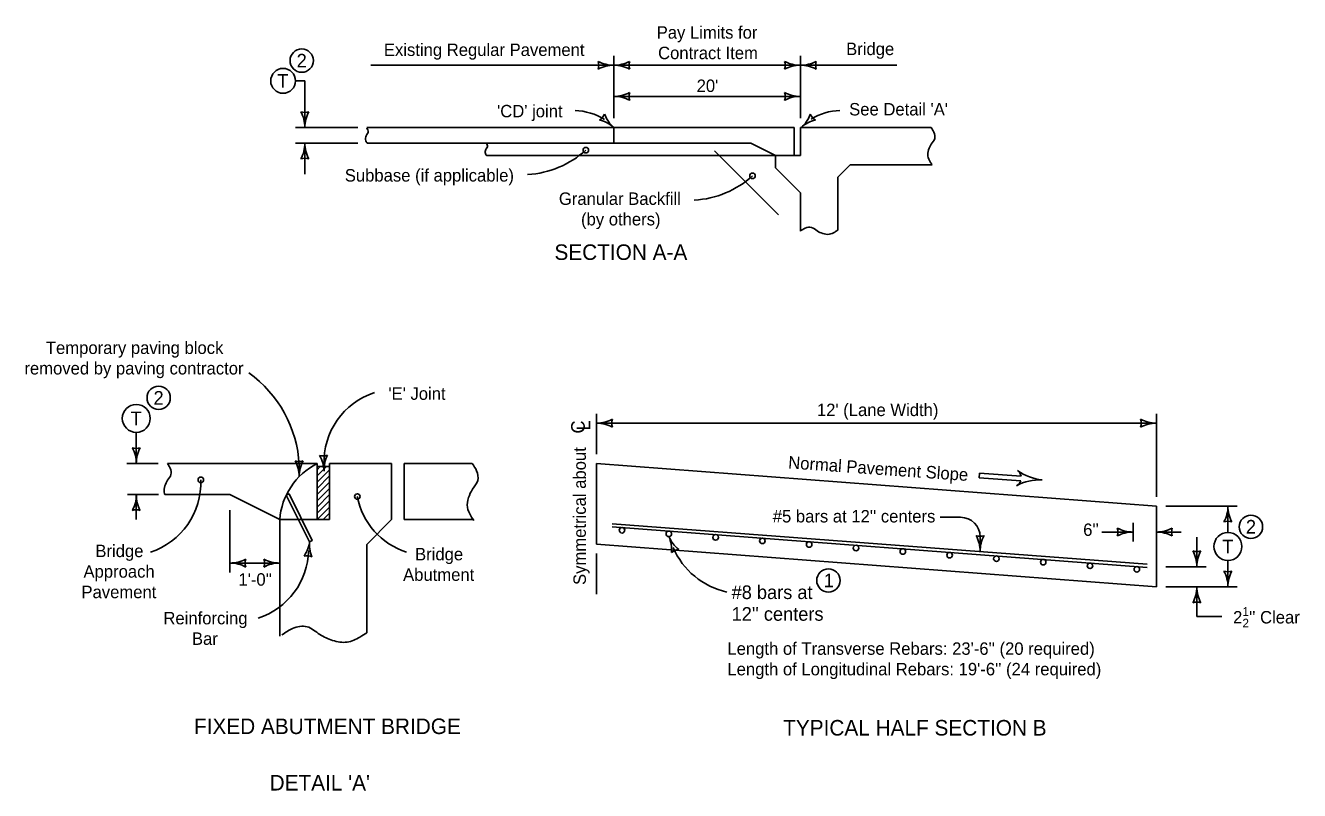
# Model space of a CAD drawing. Extents: x -2134222 to -2124595, y -2139046 to -2134021.
# Drawn here: x -2134222 to -2132583, y -2138902 to -2137918 of the extents above; entities that cross this region are included whole.
import ezdxf

# ---------------------------------------------------------------- set-up
doc = ezdxf.new("R2010")
doc.units = 0
for name, color, linetype in [('Barrier', 7, 'Continuous'), ('BridgeSuperStructureExisting', 7, 'Continuous'), ('dsnStdLabel', 7, 'Continuous'), ('hwyPlanSheetShape', 7, 'Continuous')]:
    doc.layers.add(name, color=color, linetype=linetype)

msp = doc.modelspace()

# ---------------------------------------------------------------- linework, layer by layer
at = {"layer": 'BridgeSuperStructureExisting'}
for p, q in [((-2133465.2, -2137957.4), (-2133465.2, -2138037.4)), ((-2133225.2, -2137957.4), (-2133225.2, -2138037.4)), ((-2133777.7, -2137969.4), (-2133465.2, -2137969.4)), ((-2133465.2, -2137969.4), (-2133225.2, -2137969.4)), ((-2133225.2, -2137969.4), (-2133101.2, -2137969.4)), ((-2133862.6, -2137989.4), (-2133874.6, -2137989.4)), ((-2133862.6, -2137989.4), (-2133862.6, -2138049.4)), ((-2133465.2, -2138009.4), (-2133225.2, -2138009.4)), ((-2133794.6, -2138049.4), (-2133874.6, -2138049.4)), ((-2133783.1, -2138049.4), (-2133465.2, -2138049.4)), ((-2133465.2, -2138049.4), (-2133233.2, -2138049.4)), ((-2133465.2, -2138049.4), (-2133465.2, -2138069.4)), ((-2133233.2, -2138049.4), (-2133233.2, -2138085.4)), ((-2133225.2, -2138085.4), (-2133225.2, -2138049.4)), ((-2133225.2, -2138049.4), (-2133057.2, -2138049.4)), ((-2133794.6, -2138069.4), (-2133874.6, -2138069.4)), ((-2133862.6, -2138069.4), (-2133862.6, -2138109.4)), ((-2133782.6, -2138069.4), (-2133465.2, -2138069.4)), ((-2133465.2, -2138069.4), (-2133289.2, -2138069.4)), ((-2133335.8, -2138079.3), (-2133253.4, -2138161.6)), ((-2133257.2, -2138085.4), (-2133289.2, -2138069.4)), ((-2133629, -2138085.4), (-2133257.2, -2138085.4)), ((-2133233.2, -2138085.4), (-2133257.2, -2138085.4)), ((-2133257.2, -2138085.4), (-2133257.2, -2138101.4)), ((-2133233.2, -2138085.4), (-2133225.2, -2138085.4)), ((-2133257.2, -2138101.4), (-2133225.2, -2138133.4)), ((-2133177.2, -2138113.4), (-2133161.2, -2138097.4)), ((-2133161.2, -2138097.4), (-2133055.9, -2138097.4)), ((-2133177.2, -2138113.4), (-2133177.2, -2138181.4)), ((-2133225.2, -2138133.4), (-2133225.2, -2138182.6)), ((-2133487.3, -2138469.6), (-2133487.3, -2138417.6)), ((-2132767.3, -2138522.4), (-2132767.3, -2138417.6)), ((-2132767.3, -2138524.2), (-2132767.3, -2138419.5)), ((-2133487.3, -2138429.6), (-2132767.3, -2138429.6)), ((-2134079.5, -2138441.5), (-2134079.5, -2138481.5)), ((-2134051.5, -2138481.5), (-2134091.5, -2138481.5)), ((-2134039.5, -2138481.5), (-2133847, -2138481.5)), ((-2133869.9, -2138483.3), (-2133869.9, -2138498.4)), ((-2133847, -2138481.5), (-2133847, -2138553.5)), ((-2133847, -2138497.5), (-2133835, -2138485.5)), ((-2133847, -2138489.5), (-2133843, -2138485.5)), ((-2133847, -2138485.5), (-2133831, -2138485.5)), ((-2133831, -2138553.5), (-2133831, -2138481.5)), ((-2133831, -2138481.5), (-2133751, -2138481.5)), ((-2133751, -2138553.5), (-2133751, -2138481.5)), ((-2133735, -2138481.5), (-2133647.5, -2138481.5)), ((-2133735, -2138553.5), (-2133735, -2138481.5)), ((-2133487.3, -2138481.6), (-2132767.3, -2138536.2)), ((-2133487.3, -2138481.6), (-2133487.3, -2138585.3)), ((-2133847, -2138505.5), (-2133831, -2138489.5)), ((-2133847, -2138513.5), (-2133831, -2138497.5)), ((-2133847, -2138521.5), (-2133831, -2138505.5)), ((-2132995.4, -2138500), (-2132995, -2138493.9)), ((-2132941.8, -2138503.7), (-2132995.4, -2138500)), ((-2132995, -2138493.9), (-2132941.3, -2138497.6)), ((-2134050.9, -2138521.5), (-2134090.9, -2138521.5)), ((-2134079.5, -2138521.5), (-2134079.5, -2138553.5)), ((-2134042.6, -2138521.5), (-2133959, -2138521.5)), ((-2133895, -2138553.5), (-2133959, -2138521.5)), ((-2133847, -2138529.5), (-2133831, -2138513.5)), ((-2133847, -2138537.5), (-2133831, -2138521.5)), ((-2133847, -2138545.5), (-2133831, -2138529.5)), ((-2133847, -2138553.5), (-2133831, -2138537.5)), ((-2132767.3, -2138536.2), (-2132767.3, -2138639.9)), ((-2132755.3, -2138536.2), (-2132663.3, -2138536.2)), ((-2132675.3, -2138570.2), (-2132675.3, -2138536.2)), ((-2133959, -2138541.5), (-2133959, -2138621.5)), ((-2133847, -2138553.5), (-2133895, -2138553.5)), ((-2133895, -2138553.5), (-2133895, -2138703.5)), ((-2133847, -2138553.5), (-2133831, -2138553.5)), ((-2133839, -2138553.5), (-2133831, -2138545.5)), ((-2133783, -2138585.5), (-2133751, -2138553.5)), ((-2133735, -2138553.5), (-2133645.4, -2138553.5)), ((-2133045.3, -2138550.7), (-2133019.1, -2138550.7)), ((-2133467.5, -2138558.9), (-2132779.4, -2138611.1)), ((-2133467.4, -2138562.9), (-2132779.3, -2138615.1)), ((-2132837.5, -2138569.6), (-2132797.3, -2138569.6)), ((-2132797.3, -2138581.6), (-2132797.3, -2138557.6)), ((-2132767.3, -2138569.6), (-2132735.3, -2138569.6)), ((-2133783, -2138585.5), (-2133783, -2138699.1)), ((-2133487.3, -2138585.3), (-2132767.3, -2138639.9)), ((-2132994.1, -2138594.6), (-2132994.1, -2138575.7)), ((-2132715.3, -2138614.2), (-2132715.3, -2138576.2)), ((-2133895, -2138597.5), (-2133895, -2138621.5)), ((-2133487.3, -2138649.3), (-2133487.3, -2138597.3)), ((-2133895, -2138609.5), (-2133959, -2138609.5)), ((-2132792.2, -2138610.1), (-2132792.2, -2138610.1)), ((-2132755.3, -2138614.2), (-2132703.3, -2138614.2)), ((-2132675.3, -2138640.2), (-2132675.3, -2138606.2)), ((-2132755.3, -2138640.2), (-2132663.3, -2138640.2)), ((-2132715.3, -2138678.2), (-2132715.3, -2138640.2)), ((-2132715.3, -2138678.2), (-2132683.3, -2138678.2))]:
    msp.add_line(p, q, dxfattribs=at)
msp.add_lwpolyline([(-2133886.6, -2138522.3), (-2133883, -2138520.5), (-2133853.1, -2138580.3), (-2133856.7, -2138582.1)], close=True, dxfattribs=at)
for centre, radius in [((-2133866.7, -2137963.4), 15), ((-2133890.6, -2137989.4), 16), ((-2133501.2, -2138078.5), 3.56), ((-2133286.8, -2138111.5), 3.56), ((-2134050.7, -2138397), 15), ((-2134079.5, -2138423.5), 18), ((-2133996.5, -2138502.5), 3.56), ((-2133795.1, -2138524), 3.56), ((-2132645.7, -2138562.9), 15), ((-2133454.7, -2138567.3), 3.56), ((-2133394.5, -2138571.9), 3.56), ((-2132675.3, -2138588.2), 18), ((-2133334.3, -2138576.5), 3.56), ((-2133274.1, -2138581), 3.56), ((-2133213.9, -2138585.6), 3.56), ((-2133153.7, -2138590.2), 3.56), ((-2133093.5, -2138594.7), 3.56), ((-2133033.3, -2138599.3), 3.56), ((-2132973.1, -2138603.9), 3.56), ((-2133189.2, -2138631.9), 15), ((-2132912.9, -2138608.4), 3.56), ((-2132852.7, -2138613), 3.56), ((-2132792.5, -2138617.6), 3.56)]:
    msp.add_circle(centre, radius, dxfattribs=at)
for centre, radius, start, end in [((-2133501.4, -2137969.4), 16.7, 342.2666, 17.7333), ((-2133465.2, -2137926.2), 43.2, 241.9275, 270), ((-2133465.2, -2137926.2), 43.2, 270, 298.0725), ((-2133428.9, -2137969.4), 16.7, 162.2666, 197.7334), ((-2133261.4, -2137969.4), 16.7, 342.2666, 17.7333), ((-2133225.2, -2137926.2), 43.2, 241.9275, 270), ((-2133225.2, -2137926.2), 43.2, 270, 298.0725), ((-2133188.9, -2137969.4), 16.7, 162.2666, 197.7334), ((-2133465.2, -2138012.5), 43.2, 90, 118.0725), ((-2133465.2, -2138012.5), 43.2, 61.9275, 90), ((-2133225.2, -2138012.5), 43.2, 90, 118.0725), ((-2133225.2, -2138012.5), 43.2, 61.9275, 90), ((-2133465.2, -2137966.2), 43.2, 270, 298.0725), ((-2133465.2, -2138052.5), 43.2, 61.9275, 90), ((-2133428.9, -2138009.4), 16.7, 162.2666, 197.7334), ((-2133261.4, -2138009.4), 16.7, 342.2666, 17.7333), ((-2133225.2, -2137966.2), 43.2, 241.9275, 270), ((-2133225.2, -2138052.5), 43.2, 90, 118.0725), ((-2133862.6, -2138013.2), 16.7, 252.2666, 287.7333), ((-2133905.8, -2138049.4), 43.2, 360, 28.0725), ((-2133819.4, -2138049.4), 43.2, 151.9275, 180), ((-2133516.2, -2138099), 71.3, 56.8595, 89.1101), ((-2133173.3, -2138099), 71.3, 90.8899, 122.1527), ((-2133492.4, -2138025.5), 16.7, 300.9973, 336.464), ((-2133493.6, -2138081.8), 43.2, 48.7306, 76.8031), ((-2133436.7, -2138016.9), 43.2, 200.6582, 228.7306), ((-2133252.8, -2138016.9), 43.2, 311.2694, 339.3419), ((-2133195.9, -2138081.8), 43.2, 103.1969, 131.2694), ((-2133197.2, -2138025.5), 16.7, 203.536, 239.0027), ((-2133905.8, -2138069.4), 43.2, 331.9275, 360), ((-2133819.4, -2138069.4), 43.2, 180, 208.0725), ((-2133583.1, -2137987.5), 122.5, 273.2879, 311.9844), ((-2133862.6, -2138105.6), 16.7, 72.2666, 107.7334), ((-2133368.7, -2138020.5), 122.5, 273.2879, 311.9844), ((-2134025.8, -2138491.7), 156.1, 3.0708, 54.3543), ((-2133744, -2138479.7), 94, 107.9644, 182.203), ((-2133487.3, -2138386.4), 43.2, 270, 298.0725), ((-2133487.3, -2138472.8), 43.2, 61.9275, 90), ((-2133451.1, -2138429.6), 16.7, 162.2666, 197.7334), ((-2132803.5, -2138429.6), 16.7, 342.2666, 17.7333), ((-2132767.3, -2138386.4), 43.2, 241.9275, 270), ((-2132767.3, -2138472.8), 43.2, 90, 118.0725), ((-2134079.5, -2138445.3), 16.7, 252.2666, 287.7333), ((-2134122.6, -2138481.5), 43.2, 360, 28.0725), ((-2134036.3, -2138481.5), 43.2, 151.9275, 180), ((-2133839.3, -2138455.1), 16.7, 254.4696, 289.9363), ((-2133881.1, -2138492.9), 43.2, 2.203, 30.2755), ((-2133794.8, -2138489.6), 43.2, 154.1305, 182.203), ((-2133806.6, -2138560.5), 88.7, 117.1135, 175.5063), ((-2133869.9, -2138462.2), 16.7, 252.2666, 287.7333), ((-2133913.1, -2138498.4), 43.2, 360, 28.0725), ((-2133826.7, -2138498.4), 43.2, 151.9275, 180), ((-2134090.4, -2138506.1), 94, 287.9644, 2.203), ((-2132916.8, -2138568), 65.5, 87.6842, 117.7143), ((-2132952.6, -2138499.9), 11.5, 297.7147, 340.5877), ((-2132952.6, -2138499.9), 11.5, 11.4195, 54.2853), ((-2132907.6, -2138437.4), 65.5, 234.2857, 264.3158), ((-2134122.6, -2138521.5), 43.2, 331.9275, 360), ((-2134036.3, -2138521.5), 43.2, 180, 208.0725), ((-2133702.9, -2138506.1), 94, 190.9935, 252.0356), ((-2132718.5, -2138536.2), 43.2, 331.9275, 360), ((-2132632.1, -2138536.2), 43.2, 180, 208.0725), ((-2134079.5, -2138557.7), 16.7, 72.2666, 107.7334), ((-2132833.5, -2138569.6), 16.7, 342.2666, 17.7333), ((-2132797.3, -2138526.4), 43.2, 241.9275, 270), ((-2132797.3, -2138612.8), 43.2, 90, 118.0725), ((-2132767.3, -2138526.4), 43.2, 270, 298.0725), ((-2132767.3, -2138612.8), 43.2, 61.9275, 90), ((-2132731.1, -2138569.6), 16.7, 162.2666, 197.7334), ((-2132675.3, -2138572.5), 16.7, 72.2666, 107.7334), ((-2133899.4, -2138576.4), 43.2, 326.1305, 354.203), ((-2133813.5, -2138585.1), 43.2, 174.203, 202.2755), ((-2133354.6, -2138558.6), 43.2, 202.9788, 231.0513), ((-2133434.1, -2138592.3), 43.2, 354.9063, 22.9788), ((-2132994.1, -2138558.4), 16.7, 252.2666, 287.7333), ((-2133037.3, -2138594.6), 43.2, 360, 28.0725), ((-2132950.9, -2138594.6), 43.2, 151.9275, 180), ((-2133951.7, -2138590.9), 94, 287.9644, 358.5938), ((-2133860.1, -2138616.8), 16.7, 66.4696, 101.9363), ((-2133380.2, -2138608.8), 16.7, 95.2454, 130.7121), ((-2133298, -2138550.1), 99.2, 203.5072, 257.3447), ((-2132715.3, -2138578), 16.7, 252.2666, 287.7333), ((-2132758.5, -2138614.2), 43.2, 360, 28.0725), ((-2132672.1, -2138614.2), 43.2, 151.9275, 180), ((-2133959, -2138566.3), 43.2, 270, 298.0725), ((-2133959, -2138652.7), 43.2, 61.9275, 90), ((-2133922.8, -2138609.5), 16.7, 162.2666, 197.7334), ((-2133931.2, -2138609.5), 16.7, 342.2666, 17.7333), ((-2133895, -2138566.3), 43.2, 241.9275, 270), ((-2133895, -2138652.7), 43.2, 90, 118.0725), ((-2132675.3, -2138604), 16.7, 252.2666, 287.7333), ((-2132718.5, -2138640.2), 43.2, 360, 28.0725), ((-2132632.1, -2138640.2), 43.2, 151.9275, 180), ((-2132758.5, -2138640.2), 43.2, 331.9275, 360), ((-2132672.1, -2138640.2), 43.2, 180, 208.0725), ((-2132715.3, -2138676.5), 16.7, 72.2666, 107.7334)]:
    msp.add_arc(centre, radius, start, end, dxfattribs=at)
for points in [[(-2133783.1, -2138049.9), (-2133781.6, -2138052.4), (-2133781.2, -2138055.7), (-2133783, -2138058.6), (-2133784.3, -2138061.5), (-2133784.7, -2138064.9), (-2133783.6, -2138067.8), (-2133782.6, -2138069.4)], [(-2133057.2, -2138049.4), (-2133053.5, -2138055.4), (-2133052.5, -2138063.6), (-2133056.9, -2138070.8), (-2133060.3, -2138078.1), (-2133061.2, -2138086.3), (-2133058.3, -2138093.5), (-2133055.9, -2138097.3)], [(-2133629.4, -2138069.6), (-2133628.2, -2138071.6), (-2133627.9, -2138074.3), (-2133629.3, -2138076.7), (-2133630.5, -2138079), (-2133630.8, -2138081.7), (-2133629.8, -2138084.1), (-2133629, -2138085.4)], [(-2133225.1, -2138182.6), (-2133219.1, -2138178.9), (-2133210.9, -2138178), (-2133203.7, -2138182.3), (-2133196.4, -2138185.7), (-2133188.2, -2138186.7), (-2133181, -2138183.8), (-2133177.2, -2138181.4)], [(-2134039.5, -2138481.5), (-2134035.8, -2138487.6), (-2134034.9, -2138495.7), (-2134039.2, -2138503), (-2134042.6, -2138510.2), (-2134043.5, -2138518.4), (-2134042.6, -2138521.5)], [(-2133647.3, -2138481.6), (-2133641.7, -2138490.8), (-2133640.3, -2138503.3), (-2133646.9, -2138514.4), (-2133652, -2138525.4), (-2133653.5, -2138537.9), (-2133649.1, -2138548.9), (-2133645.4, -2138554.8)], [(-2133892.2, -2138701.9), (-2133878.5, -2138693.6), (-2133859.8, -2138691.4), (-2133843.4, -2138701.3), (-2133826.9, -2138709), (-2133808.3, -2138711.2), (-2133791.8, -2138704.6), (-2133783, -2138699.1)]]:
    msp.add_spline(points, degree=3, dxfattribs=at)
at = {"layer": 'dsnStdLabel'}
msp.add_arc((-2133019.1, -2138575.7), 25, 0, 90, dxfattribs=at)

# ---------------------------------------------------------------- texts
at = {"layer": 'Barrier'}
for p in [(-2133873.2, -2137972.2), (-2134057.3, -2138405.8), (-2132652.2, -2138571.6)]:
    msp.add_text('2', height=17.5, dxfattribs=at).set_placement(p)
at = {"layer": 'dsnStdLabel'}
for s, height, p in [('Pay Limits for', 16, (-2133410.1, -2137935.1)), ('Existing Regular Pavement', 16, (-2133761, -2137957.4)), ('Contract Item', 16, (-2133408.3, -2137961.5)), ('Bridge', 16, (-2133166.4, -2137956.3)), ('T', 17.5, (-2133898, -2137998.1)), ("20'", 16, (-2133358.7, -2138003.7)), ("'CD' joint", 16, (-2133615.4, -2138036.3)), ("See Detail 'A'", 16, (-2133162.5, -2138033.9)), ('Subbase (if applicable)', 16, (-2133811.3, -2138118.9)), ('Granular Backfill', 16, (-2133535.9, -2138148.9)), ('(by others)', 16, (-2133507.4, -2138175.3)), ('SECTION A-A', 20, (-2133541.6, -2138219.7)), ('Temporary paving block', 16, (-2134195.8, -2138340.6)), ('removed by paving contractor', 16, (-2134223.4, -2138367)), ("'E' Joint", 16, (-2133755.2, -2138399.6)), ("12' (Lane Width)", 16, (-2133204, -2138420.5)), ('T', 17.5, (-2134086.8, -2138432.3)), ("#5 bars at 12'' centers", 16, (-2133260.8, -2138557.3)), ("6''", 16, (-2132861.5, -2138574.6)), ('Bridge', 16, (-2134132.1, -2138601.9)), ('T', 17.5, (-2132682.7, -2138597)), ('Bridge', 16, (-2133720.9, -2138606)), ('Approach', 16, (-2134147.4, -2138628.3)), ('Abutment', 16, (-2133736.3, -2138632.4)), ("1'-0''", 16, (-2133948.1, -2138638.6)), ('1', 17.5, (-2133195.2, -2138640.6)), ('Pavement', 16, (-2134150, -2138654.7)), ('#8 bars at ', 17.5, (-2133313.7, -2138655.8)), ("12'' centers", 17.5, (-2133313.7, -2138683.7)), ('Reinforcing', 16, (-2134044.6, -2138688.3)), ('Bar', 16, (-2134007.9, -2138714.7)), ("Length of Transverse Rebars: 23'-6'' (20 required)", 16, (-2133319.1, -2138727.5)), ("Length of Longitudinal Rebars: 19'-6'' (24 required)", 16, (-2133319.1, -2138753.9)), ('FIXED ABUTMENT BRIDGE', 20, (-2134005.3, -2138829.4)), ('TYPICAL HALF SECTION B', 20, (-2133247.4, -2138831.3)), ("DETAIL 'A'", 20, (-2133908, -2138902))]:
    msp.add_text(s, height=height, dxfattribs=at).set_placement(p)
for s, height, rotation, p in [('C', 17.5, 90, (-2133502.6, -2138443)), ('L', 17.5, 90, (-2133495.6, -2138439.1)), ('Symmetrical about', 16, 90, (-2133501.2, -2138637.7)), ('Normal Pavement Slope', 16, 356, (-2133241.3, -2138487.8))]:
    msp.add_text(s, height=height, rotation=rotation, dxfattribs=at).set_placement(p)
at = {"layer": 'hwyPlanSheetShape'}
for s, height, p in [('1', 11.2, (-2132656.6, -2138677.4)), ('2', 16, (-2132668.7, -2138687.2)), ('2', 11.2, (-2132656.6, -2138692.3)), ("'' Clear", 16, (-2132648.1, -2138687.2))]:
    msp.add_text(s, height=height, dxfattribs=at).set_placement(p)

doc.saveas('drawing.dxf')
